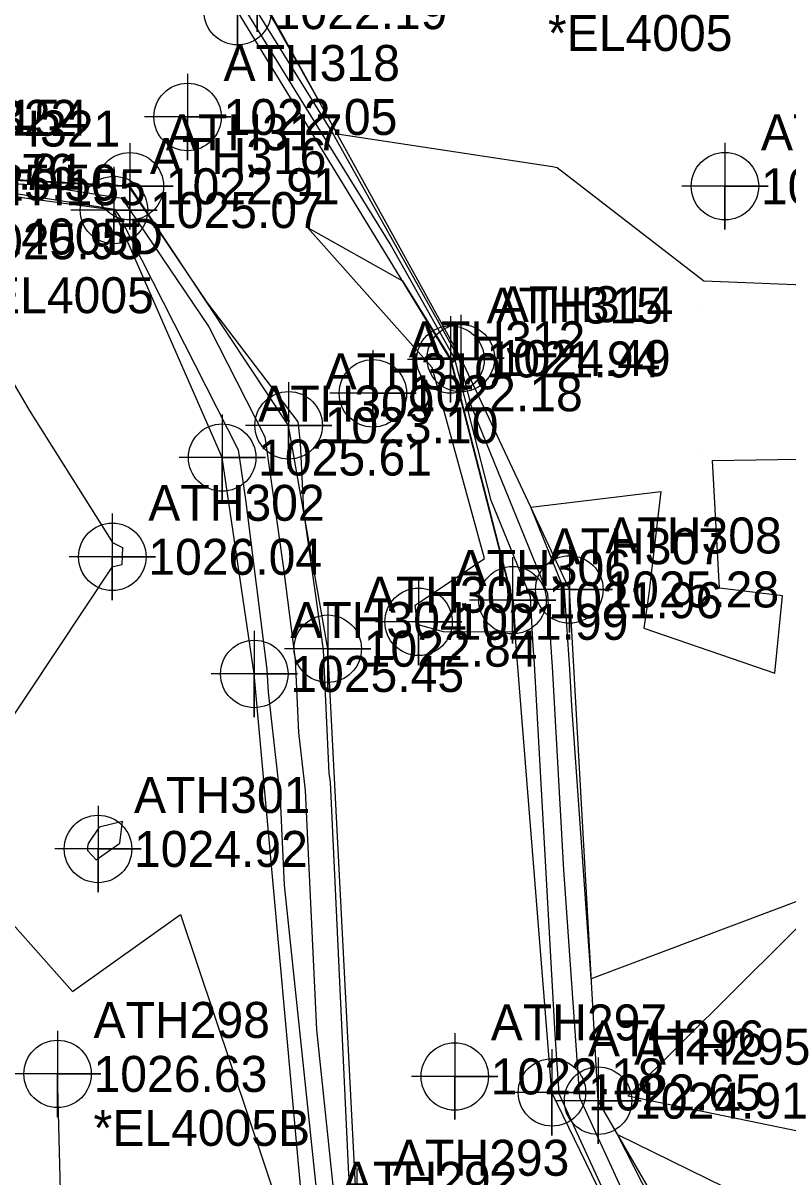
# Model space of a CAD drawing. Extents: x 1213164 to 1213550, y 766120 to 766870.
# Drawn here: x 1213353.1 to 1213406.3, y 766399.6 to 766479.8 of the extents above; entities that cross this region are included whole.
import ezdxf

# ---------------------------------------------------------------- set-up
doc = ezdxf.new("R2010")
doc.units = 0
for name, color, linetype in [('Default', 7, 'Continuous'), ('Exist DTM Breakline', 7, 'Continuous'), ('Exist DTM Breakline Cogo Comment', 7, 'Continuous'), ('Exist DTM Breakline Cogo Elevation', 7, 'Continuous'), ('Exist DTM Breakline Cogo Number', 7, 'Continuous'), ('Exist DTM Breakline Cogo Point CELL', 7, 'Continuous'), ('Exist DTM Crownline', 7, 'Continuous'), ('Exist DTM Drainline Cogo Elevation', 7, 'Continuous'), ('Exist DTM Drainline Cogo Number', 7, 'Continuous'), ('Exist DTM Drainline Cogo Point CELL', 7, 'Continuous'), ('Exist DTM QL2 LIDAR Elevation Point', 7, 'Continuous'), ('Exist DTM Regular Point CELL', 7, 'Continuous'), ('Exist DTM Regular Point Cogo Elevation', 7, 'Continuous'), ('Exist DTM Regular Point Cogo Number', 7, 'Continuous'), ('Exist DTM Regular Point Underwater CELL', 7, 'Continuous'), ('Exist DTM Regular Point Underwater Cogo Elevation', 7, 'Continuous'), ('Exist DTM Regular Point Underwater Cogo Number', 7, 'Continuous'), ('Exist Hydro Stream or Body of Water', 7, 'Continuous'), ('Exist Roads EOP', 7, 'Continuous')]:
    doc.layers.add(name, color=color, linetype=linetype)

msp = doc.modelspace()

# ---------------------------------------------------------------- linework, layer by layer
at = {"layer": 'Default'}
for points in [[(1213300.885, 766515.957), (1213316.743, 766510.012), (1213318.331, 766512.154), (1213319.064, 766511.902), (1213321.218, 766513.267), (1213325.627, 766510.661), (1213339.551, 766506.025), (1213348.137, 766501.785), (1213349.431, 766499.539), (1213350.558, 766498.57), (1213361.343, 766489.111), (1213368.811, 766481.534), (1213374.658, 766472.092), (1213383.401, 766456.504), (1213384.24, 766453.245), (1213389.563, 766440.166), (1213389.659, 766438.461), (1213389.891, 766435.088), (1213390.675, 766420.964), (1213391.789, 766405.168), (1213396.624, 766394.628)], [(1213369.246, 766482.036), (1213370.687, 766479.709), (1213374.95, 766472.108), (1213389.92, 766469.834), (1213390.244, 766469.756), (1213400.423, 766461.889), (1213408.51, 766461.558)], [(1213398.21, 766388.346), (1213390.376, 766405.42), (1213390.085, 766409.559), (1213388.658, 766435.251), (1213388.545, 766436.902), (1213388.374, 766439.941), (1213385.654, 766446.624), (1213383.119, 766456.468), (1213378.629, 766464.474), (1213368.376, 766481.032)], [(1213342.98, 766469.415), (1213359.97, 766468.473), (1213360.485, 766468.391), (1213365.911, 766460.372), (1213372.206, 766452.096), (1213372.381, 766450.629), (1213372.615, 766445.885), (1213373.864, 766437.103), (1213373.975, 766436.228), (1213374.375, 766427.694), (1213374.446, 766427.072), (1213375.738, 766399.82), (1213376.025, 766397.096)], [(1213343.828, 766469.139), (1213354.03, 766468.573), (1213359.975, 766467.627), (1213366.021, 766458.69), (1213369.912, 766451.051), (1213371.213, 766441.9), (1213372.02, 766435.557), (1213372.257, 766430.505), (1213372.712, 766426.484), (1213373.5, 766409.86), (1213374.896, 766396.617)], [(1213348.091, 766468.673), (1213359.464, 766466.862), (1213359.854, 766466.285), (1213368.071, 766450.158), (1213368.563, 766446.698), (1213370.065, 766434.886), (1213370.138, 766433.315), (1213370.978, 766425.896), (1213371.262, 766419.9), (1213373.766, 766396.139)], [(1213372.885, 766465.59), (1213379.481, 766461.894), (1213382.6, 766456.857), (1213382.838, 766456.432), (1213387.068, 766440.004), (1213387.186, 766439.716), (1213387.311, 766437.475), (1213382.329, 766437.5), (1213380.503, 766438.017), (1213380.498, 766438.172), (1213380.488, 766438.375), (1213380.371, 766439.355), (1213385.183, 766442.594), (1213381.537, 766455.87), (1213372.885, 766465.59)], [(1213346.7, 766464.579), (1213353.528, 766452.918), (1213359.319, 766443.712), (1213360.021, 766443.358), (1213359.984, 766442.167), (1213359.279, 766441.998), (1213349.493, 766427.323)], [(1213390.752, 766440.391), (1213388.405, 766446.158), (1213397.441, 766447.26), (1213396.608, 766440.172), (1213396.248, 766437.771), (1213405.356, 766434.644), (1213405.894, 766440), (1213401.509, 766440.547), (1213401.039, 766449.417), (1213410.06, 766449.559)], [(1213410.209, 766402.141), (1213395.157, 766405.24), (1213409.903, 766419.914), (1213392.602, 766413.403), (1213391.265, 766432.37), (1213391.123, 766434.924), (1213390.773, 766440.02), (1213390.752, 766440.391)], [(1213360.027, 766424.335), (1213358.396, 766423.943), (1213357.638, 766422.805), (1213357.593, 766422.571), (1213357.592, 766422.324), (1213358.184, 766421.658), (1213359.835, 766422.833), (1213360.027, 766424.335)], [(1213348.9, 766421.116), (1213356.538, 766412.518), (1213364.052, 766417.862), (1213371.178, 766396.675)], [(1213402.95, 766385.888), (1213394.44, 766402.585), (1213408.127, 766395.879)]]:
    msp.add_lwpolyline(points, dxfattribs=at)
at = {"layer": 'Exist DTM Breakline'}
for points in [[(1213458.364, 766304.665), (1213456.152, 766280.485), (1213457.947, 766246.9), (1213447.467, 766261.797), (1213441.278, 766307.974), (1213433.945, 766370.733), (1213403.815, 766386.389), (1213393.078, 766404.937), (1213391.083, 766440.453), (1213383.54, 766456.522), (1213369.388, 766482.2), (1213351.856, 766502.119)], [(1213525.393, 766207.467), (1213482.007, 766225.047), (1213449.305, 766226.194), (1213431.701, 766256.624), (1213419.176, 766304.878), (1213413.481, 766348.824), (1213382.307, 766373.433), (1213372.705, 766395.689), (1213369.183, 766434.583), (1213366.951, 766449.615), (1213359.429, 766466.809), (1213345.103, 766468.723)], [(1213448.716, 766182.984), (1213435.665, 766212.973), (1213412.223, 766248.511), (1213393.848, 766299.084), (1213370.867, 766342.586), (1213356.515, 766367.11), (1213355.508, 766406.797)]]:
    msp.add_lwpolyline(points, dxfattribs=at)
at = {"layer": 'Exist DTM Breakline Cogo Point CELL'}
for points in [[(1213369.388, 766485.2), (1213369.388, 766479.2), (1213369.388, 766482.2), (1213372.388, 766482.2), (1213366.388, 766482.2)], [(1213359.429, 766469.809), (1213359.429, 766463.809), (1213359.429, 766466.809), (1213362.429, 766466.809), (1213356.429, 766466.809)], [(1213383.54, 766459.522), (1213383.54, 766453.522), (1213383.54, 766456.522), (1213386.54, 766456.522), (1213380.54, 766456.522)], [(1213366.951, 766452.615), (1213366.951, 766446.615), (1213366.951, 766449.615), (1213369.951, 766449.615), (1213363.951, 766449.615)], [(1213391.083, 766443.453), (1213391.083, 766437.453), (1213391.083, 766440.453), (1213394.083, 766440.453), (1213388.083, 766440.453)], [(1213369.183, 766437.583), (1213369.183, 766431.583), (1213369.183, 766434.583), (1213372.183, 766434.583), (1213366.183, 766434.583)], [(1213355.508, 766409.797), (1213355.508, 766403.797), (1213355.508, 766406.797), (1213358.508, 766406.797), (1213352.508, 766406.797)], [(1213393.078, 766407.937), (1213393.078, 766401.937), (1213393.078, 766404.937), (1213396.078, 766404.937), (1213390.078, 766404.937)]]:
    msp.add_lwpolyline(points, dxfattribs=at)
for centre in [(1213359.429, 766466.809), (1213383.54, 766456.522), (1213366.951, 766449.615), (1213391.083, 766440.453), (1213369.183, 766434.583), (1213355.508, 766406.797), (1213393.078, 766404.937)]:
    msp.add_circle(centre, 2.344, dxfattribs=at)
at = {"layer": 'Exist DTM Crownline'}
msp.add_spline([(1213364.822, 766294.526), (1213349.913, 766319.907), (1213339.177, 766339.489), (1213331.697, 766355.273), (1213321.978, 766382.664), (1213317.523, 766424.054), (1213319.575, 766440.21), (1213325.279, 766470.159)], degree=3, dxfattribs=at)
at = {"layer": 'Exist DTM Drainline Cogo Point CELL'}
for points in [[(1213368.024, 766483.627), (1213368.024, 766477.627), (1213368.024, 766480.627), (1213371.024, 766480.627), (1213365.024, 766480.627)], [(1213360.534, 766471.464), (1213360.534, 766465.464), (1213360.534, 766468.464), (1213363.534, 766468.464), (1213357.534, 766468.464)], [(1213382.822, 766459.43), (1213382.822, 766453.43), (1213382.822, 766456.43), (1213385.822, 766456.43), (1213379.822, 766456.43)], [(1213371.57, 766454.854), (1213371.57, 766448.854), (1213371.57, 766451.854), (1213374.57, 766451.854), (1213368.57, 766451.854)], [(1213387.132, 766442.706), (1213387.132, 766436.706), (1213387.132, 766439.706), (1213390.132, 766439.706), (1213384.132, 766439.706)], [(1213374.288, 766439.335), (1213374.288, 766433.335), (1213374.288, 766436.335), (1213377.288, 766436.335), (1213371.288, 766436.335)], [(1213389.875, 766408.51), (1213389.875, 766402.51), (1213389.875, 766405.51), (1213392.875, 766405.51), (1213386.875, 766405.51)], [(1213376.318, 766400.22), (1213376.318, 766394.22), (1213376.318, 766397.22), (1213379.318, 766397.22), (1213373.318, 766397.22)]]:
    msp.add_lwpolyline(points, dxfattribs=at)
for centre in [(1213368.024, 766480.627), (1213360.534, 766468.464), (1213382.822, 766456.43), (1213371.57, 766451.854), (1213387.132, 766439.706), (1213374.288, 766436.335), (1213389.875, 766405.51)]:
    msp.add_circle(centre, 2.344, dxfattribs=at)
at = {"layer": 'Exist DTM QL2 LIDAR Elevation Point'}
for p, q in [((1213390, 766470), (1213390, 766470)), ((1213400, 766460), (1213400, 766460)), ((1213400, 766450), (1213400, 766450)), ((1213400, 766440), (1213400, 766440))]:
    msp.add_line(p, q, dxfattribs=at)
at = {"layer": 'Exist DTM Regular Point CELL'}
for points in [[(1213401.898, 766471.469), (1213401.898, 766465.469), (1213401.898, 766468.469), (1213404.898, 766468.469), (1213398.898, 766468.469)], [(1213359.314, 766445.72), (1213359.314, 766439.72), (1213359.314, 766442.72), (1213362.314, 766442.72), (1213356.314, 766442.72)], [(1213358.322, 766425.426), (1213358.322, 766419.426), (1213358.322, 766422.426), (1213361.322, 766422.426), (1213355.322, 766422.426)]]:
    msp.add_lwpolyline(points, dxfattribs=at)
for centre in [(1213401.898, 766468.469), (1213359.314, 766442.72), (1213358.322, 766422.426)]:
    msp.add_circle(centre, 2.344, dxfattribs=at)
at = {"layer": 'Exist DTM Regular Point Underwater CELL'}
for points in [[(1213364.545, 766476.278), (1213364.545, 766470.278), (1213364.545, 766473.278), (1213367.545, 766473.278), (1213361.545, 766473.278)], [(1213377.428, 766457.081), (1213377.428, 766451.081), (1213377.428, 766454.081), (1213380.428, 766454.081), (1213374.428, 766454.081)], [(1213380.601, 766441.203), (1213380.601, 766435.203), (1213380.601, 766438.203), (1213383.601, 766438.203), (1213377.601, 766438.203)], [(1213383.117, 766409.621), (1213383.117, 766403.621), (1213383.117, 766406.621), (1213386.117, 766406.621), (1213380.117, 766406.621)]]:
    msp.add_lwpolyline(points, dxfattribs=at)
for centre in [(1213364.545, 766473.278), (1213377.428, 766454.081), (1213380.601, 766438.203), (1213383.117, 766406.621)]:
    msp.add_circle(centre, 2.344, dxfattribs=at)
at = {"layer": 'Exist Hydro Stream or Body of Water'}
for points in [[(1213462.585, 766303.681), (1213457.242, 766280.725), (1213458.541, 766244.269), (1213446.982, 766261.332), (1213440.132, 766307.328), (1213429.645, 766367.831), (1213400.182, 766384.285), (1213389.875, 766405.51), (1213387.132, 766439.706), (1213382.822, 766456.43), (1213368.024, 766480.627), (1213349.519, 766498.124), (1213324.243, 766505.779)], [(1213528.184, 766208.953), (1213518.126, 766232.156), (1213482.648, 766228.638), (1213450.602, 766228.856), (1213434.621, 766256.535), (1213425.001, 766305.328), (1213420.53, 766356.324), (1213385.097, 766376.623), (1213376.318, 766397.22), (1213374.288, 766436.335), (1213371.57, 766451.854), (1213360.534, 766468.464), (1213342.815, 766469.469)]]:
    msp.add_lwpolyline(points, dxfattribs=at)
at = {"layer": 'Exist Roads EOP'}
msp.add_spline([(1213331.542, 766460.381), (1213328.202, 766439.131), (1213326.882, 766418.055), (1213328.894, 766392.003), (1213339.56, 766359.268), (1213347.201, 766343.262), (1213357.639, 766324.019), (1213372.578, 766298.933)], degree=3, dxfattribs=at)

# ---------------------------------------------------------------- texts
at = {"layer": 'Exist DTM Breakline Cogo Comment'}
for s, p in [('*EL4005', (1213389.594, 766477.859)), ('*EL4005D', (1213347.603, 766463.723)), ('*EL4005', (1213349.374, 766459.646)), ('*EL4005B', (1213358.008, 766401.797))]:
    msp.add_text(s, height=2.5, dxfattribs=at).set_placement(p)
at = {"layer": 'Exist DTM Breakline Cogo Elevation'}
for s, p in [('1022.81', (1213345.315, 766468.219)), ('1025.50', (1213347.603, 766467.473)), ('1025.07', (1213361.929, 766465.559)), ('1025.95', (1213349.374, 766463.396)), ('1024.49', (1213386.04, 766455.272)), ('1025.61', (1213369.451, 766448.365)), ('1025.28', (1213393.583, 766439.203)), ('1025.45', (1213371.683, 766433.333)), ('1026.63', (1213358.008, 766405.547)), ('1024.91', (1213395.578, 766403.687))]:
    msp.add_text(s, height=2.5, dxfattribs=at).set_placement(p)
at = {"layer": 'Exist DTM Breakline Cogo Number'}
for s, p in [('ATH154', (1213345.315, 766471.969)), ('ATH321', (1213347.603, 766471.223)), ('ATH316', (1213361.929, 766469.309)), ('ATH155', (1213349.374, 766467.146)), ('ATH314', (1213386.04, 766459.022)), ('ATH309', (1213369.451, 766452.115)), ('ATH308', (1213393.583, 766442.953)), ('ATH304', (1213371.683, 766437.083)), ('ATH298', (1213358.008, 766409.297)), ('ATH295', (1213395.578, 766407.437)), ('ATH292', (1213375.205, 766398.189))]:
    msp.add_text(s, height=2.5, dxfattribs=at).set_placement(p)
at = {"layer": 'Exist DTM Drainline Cogo Elevation'}
for s, p in [('1022.19', (1213370.524, 766479.377)), ('1022.76', (1213344.613, 766468.213)), ('1022.91', (1213363.034, 766467.214)), ('1021.94', (1213385.322, 766455.18)), ('1023.10', (1213374.07, 766450.604)), ('1021.96', (1213389.632, 766438.456)), ('1022.84', (1213376.788, 766435.085)), ('1022.65', (1213392.375, 766404.26))]:
    msp.add_text(s, height=2.5, dxfattribs=at).set_placement(p)
at = {"layer": 'Exist DTM Drainline Cogo Number'}
for s, p in [('ATH322', (1213344.613, 766471.963)), ('ATH317', (1213363.034, 766470.964)), ('ATH315', (1213385.322, 766458.93)), ('ATH310', (1213374.07, 766454.354)), ('ATH307', (1213389.632, 766442.206)), ('ATH305', (1213376.788, 766438.835)), ('ATH296', (1213392.375, 766408.01)), ('ATH293', (1213378.818, 766399.72))]:
    msp.add_text(s, height=2.5, dxfattribs=at).set_placement(p)
at = {"layer": 'Exist DTM Regular Point Cogo Elevation'}
for s, p in [('1025.88', (1213404.398, 766467.219)), ('1026.04', (1213361.814, 766441.47)), ('1024.92', (1213360.822, 766421.176))]:
    msp.add_text(s, height=2.5, dxfattribs=at).set_placement(p)
at = {"layer": 'Exist DTM Regular Point Cogo Number'}
for s, p in [('ATH313', (1213404.398, 766470.969)), ('ATH302', (1213361.814, 766445.22)), ('ATH301', (1213360.822, 766424.926))]:
    msp.add_text(s, height=2.5, dxfattribs=at).set_placement(p)
at = {"layer": 'Exist DTM Regular Point Underwater Cogo Elevation'}
for s, p in [('1022.05', (1213367.045, 766472.028)), ('1022.18', (1213379.928, 766452.831)), ('1021.99', (1213383.101, 766436.953)), ('1022.18', (1213385.617, 766405.371))]:
    msp.add_text(s, height=2.5, dxfattribs=at).set_placement(p)
at = {"layer": 'Exist DTM Regular Point Underwater Cogo Number'}
for s, p in [('ATH318', (1213367.045, 766475.778)), ('ATH312', (1213379.928, 766456.581)), ('ATH306', (1213383.101, 766440.703)), ('ATH297', (1213385.617, 766409.121))]:
    msp.add_text(s, height=2.5, dxfattribs=at).set_placement(p)

doc.saveas('drawing.dxf')
